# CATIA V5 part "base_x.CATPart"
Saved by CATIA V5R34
Part number: Part2
Bounding box of the stored display mesh (mm): x -37.1 to 14, y -14 to 32, z -13.1 to 13.1
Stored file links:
  C:\Users\Apolinar\Desktop\cnc\base_x.CATPart
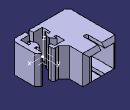
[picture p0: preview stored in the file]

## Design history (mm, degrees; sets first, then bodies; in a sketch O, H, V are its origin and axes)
AxisSystem1: origin (0, 0, 0), X (1, 0, 0), Y (0, 1, 0), Z (0, 0, 1)
Body1 (main body)
  DatumSurface1 to DatumSurface3
  DatumCurve1
  DatumPoint1
  DatumCurve2
  DatumCurve3
  DatumSurface4
  DatumCurve4
  Sketch1 on XY plane of AxisSystem1, origin (0, 0, 0), H (1, 0, 0), V (0, 1, 0)
    point P1 (-11.55, 0)
    line L1 (14, 10) -> (14, -14)
    line L2 (14, -14) -> (-37.1, -14)
    line L3 (-37.1, -14) -> (-37.1, 12)
    line L4 (-37.1, 12) -> (1.95, 12)
    reference intersected line E1 (-8.5, 10) -> (-3.75, 10) from face of DatumSurface1
    reference intersected line E2 (10, -3.75) -> (10, -8.5) from face of DatumSurface2
    line L5 (10, 10) -> (10, 2.5)
    line L6 (10, -10) -> (-10, -10)
    line L7 (-10, -10) -> (-10, -2.5)
    line L8 (-10, 10) -> (-1.05, 10)
    point P7 (-10, -10)
    point P8 (-10, 10)
    reference intersected line E3 through (-33.1, 0) direction (0, 1) from face of DatumSurface3
    point P9 (-10, 2.5)
    line L9 (-10, 2.5) -> (-8, 2.5)
    point P10 (-8, 2.5)
    point P11 (-8, -2.5)
    line L10 (-8, -2.5) -> (-10, -2.5)
    point P12 (-10, -2.5)
    line L11 (-10, 2.5) -> (-10, 10)
    line L12 (-1.05, 10) -> (-1.05, 6.5)
    line L13 (-1.05, 6.5) -> (1.95, 6.5)
    line L14 (1.95, 6.5) -> (1.95, 12)
    reference projected line E4 (-3.05, 9) -> (-3.05, 9.3) from edge of DatumCurve3
    line L15 (10, 10) -> (14, 10)
    reference intersected line E5 (3.75, 10) -> (8.5, 10) from face of DatumSurface4
    reference projected line E6 (-0.9196, 4.5) -> (-3.2919, 4.5) from edge of DatumCurve4
    point P18 (10, -2.5)
    point P19 (10, 2.5)
    line L16 (10, -2.5) -> (10, -10)
    line L17 (-8, 2.5) -> (-8, 5.5)
    point P20 (-8, 5.5)
    line L18 (-8, 5.5) -> (-5, 1.5)
    point P21 (-5, 1.5)
    line L19 (-5, 1.5) -> (-5, 0)
    point P22 (-5, 0)
    point P23 (-8, -5.5)
    point P24 (-8, -2.5)
    line L20 (-8, -2.5) -> (-8, -5.5)
    point P25 (-5, -1.5)
    line L21 (-8, -5.5) -> (-5, -1.5)
    point P26 (-5, 0)
    line L22 (-5, -1.5) -> (-5, 0)
    point P27 (0, 0)
    point P28 (8, 2.5)
    point P29 (8, -2.5)
    point P30 (8, 5.5)
    point P31 (5, 1.5)
    point P32 (5, 0)
    point P33 (8, -5.5)
    point P34 (8, -2.5)
    point P35 (5, -1.5)
    point P36 (5, 0)
    line L23 (8, 2.5) -> (8, 5.5)
    line L24 (8, 5.5) -> (5, 1.5)
    line L25 (5, 1.5) -> (5, 0)
    line L26 (8, -2.5) -> (8, -5.5)
    line L27 (8, -5.5) -> (5, -1.5)
    line L28 (5, -1.5) -> (5, 0)
    point P37 (10, 2.5)
    line L29 (10, 2.5) -> (8, 2.5)
    point P38 (10, -2.5)
    line L30 (8, -2.5) -> (10, -2.5)
    distance E1 L4 = 2
    distance E2 L1 = 4
    length L6 = 20
    distance E3 L3 = 4
    distance L6 L2 = 4
    length L9 = 2
    distance P7 P8 = 20
    distance E4 L12 = 2
    length L13 = 3
    distance L13 E6 = 2
    distance L9 H = 2.5
    distance H P21 = 1.5
    distance L17 L19 = 3
    distance P20 H = 5.5
    coincidence: P1 H, P9 L7, L7 L11, L15 E5, L5 L16, P22 H, P11 P24
    horizontal: L2 H, L4 H, L6 H, L8 H, L9 H, L10 H, L13 H, L15 H
    vertical: L3 V, L5 V, L7 V, L11 V, L12 V, L14 V, L17 V, L19 V
    equidistance: L1 L3 P1, L5 L7 O, L6 L8 O
    symmetry: P12 P18 V, P9 P19 V, P20 P23 H, P10 P24 H, L17 L20 H, P21 P25 H, L18 L21 H, P22 P26 H, L19 L22 H, O P27 V, P10 P28 V, P11 P29 V, P20 P30 V, P21 P31 V, P22 P32 V, P23 P33 V, P24 P34 V, P25 P35 V, P26 P36 V, L17 L23 V, L18 L24 V, L19 L25 V, L20 L26 V, L21 L27 V, L22 L28 V, P9 P37 V, L9 L29 V, P12 P38 V, L10 L30 V
  Pad1: profile Sketch1, direction (0, 0, 1), length 13.1, mirrored extent
  DatumSurface5
  Sketch2 on face of Pad1, origin (0, 13.2, 0), H (-1, 0, 0), V (0, 0, 1)
    point P1 (22.95, 0)
    line L1 (33.1, 10.15) -> (33.1, -10.15)
    line L2 (33.1, -10.15) -> (12.8, -10.15)
    line L3 (12.8, -10.15) -> (12.8, 10.15)
    line L4 (12.8, 10.15) -> (33.1, 10.15)
    reference intersected line E1 (33.1, 8.45) -> (33.1, 3.7) from face of DatumSurface5
    length L4 = 20.3
    length L1 = 20.3
    coincidence: P1 H, L1 E1
    vertical: L1 V, L3 V
    horizontal: L2 H, L4 H
    equidistance: L1 L3 P1, L2 L4 P1
  Pocket1: profile Sketch2, direction (0, -1, 0), length 23
  Sketch3 on face of Pad1 from Sketch1.L4, origin (0, 12, 0), H (-1, 0, 0), V (0, 0, 1)
    construction line L1 (0, 5.1) -> (0, 13.1)
    point P1 (0, 5.1)
    point P2 (0, 13.1)
    line L2 (-1.75, 5.1) -> (-1.75, 13.1)
    line L3 (1.75, 13.1) -> (1.75, 5.1)
    arc A1 centre (0, 13.1) radius 1.75 from (-1.75, 13.1) to (1.75, 13.1) cw
    arc A2 centre (0, 5.1) radius 1.75 from (1.75, 5.1) to (-1.75, 5.1) cw
    point P3 (-1.75, 5.1)
    point P4 (-1.75, 13.1)
    point P5 (1.75, 13.1)
    point P6 (1.75, 5.1)
    reference projected line E1 (-1.95, 13.1) -> (37.1, 13.1) from edge [face of Pad1 from Sketch1.L4 | end face of Pad1]
    construction line L4 (0, -5.1) -> (0, -13.1)
    point P9 (-1.75, -5.1)
    point P10 (-1.75, -13.1)
    point P11 (1.75, -13.1)
    point P12 (1.75, -5.1)
    line L5 (-1.75, -5.1) -> (-1.75, -13.1)
    line L6 (1.75, -13.1) -> (1.75, -5.1)
    arc A3 centre (0, -13.1) radius 1.75 from (-1.75, -13.1) to (1.75, -13.1) ccw
    arc A4 centre (0, -5.1) radius 1.75 from (1.75, -5.1) to (-1.75, -5.1) ccw
    distance L1 L2 = 1.75
    length L1 = 8
    coincidence: P1 V, P2 E1
    vertical: L1 V
    tangency: A1 L2, A2 L2, A1 L3, A2 L3
    symmetry: L1 L4 H, P3 P9 H, P4 P10 H, P5 P11 H, P6 P12 H, L2 L5 H, L3 L6 H, A1 A3 H, A2 A4 H
  Pocket2: profile Sketch3, direction (0, -1, 0), length 30, opposite side length -10
  DatumCurve5
  Sketch4 on face of Pad1 from Sketch1.L4, origin (0, 12, 0), H (-1, 0, 0), V (0, 0, 1)
    point P1 (22.45, 0)
    line L1 (37.1, 13.1) -> (37.1, -13.1)
    line L2 (37.1, -13.1) -> (7.8, -13.1)
    line L3 (7.8, -13.1) -> (7.8, 13.1)
    line L4 (7.8, 13.1) -> (37.1, 13.1)
    reference projected line E1 (-1.95, 13.1) -> (37.1, 13.1) from edge [face of Pad1 from Sketch1.L4 | end face of Pad1]
    reference projected line E2 (37.1, -13.1) -> (37.1, 13.1) from edge [face of Pad1 from Sketch1.L3 | face of Pad1 from Sketch1.L4]
    reference projected line E3 (12.8, -10.15) -> (12.8, 10.15) from edge [face of Pocket1 from Sketch2.L3 | face of Pad1 from Sketch1.L4]
    point P6 (22.95, 0)
    line L5 (33.1, 10.15) -> (33.1, -10.15)
    line L6 (33.1, -10.15) -> (12.8, -10.15)
    line L7 (12.8, -10.15) -> (12.8, 10.15)
    line L8 (12.8, 10.15) -> (33.1, 10.15)
    reference projected line E4 (12.8, 10.15) -> (33.1, 10.15) from edge [face of Pocket1 from Sketch2.L4 | face of Pad1 from Sketch1.L4]
    reference projected line E5 (33.1, 10.15) -> (33.1, -10.15) from edge [face of Pocket1 from Sketch2.L1 | face of Pad1 from Sketch1.L4]
    distance L3 E3 = 5
    coincidence: P1 H, L4 E1, E2 L1, P6 H, E4 L8, L5 E5, E3 L7
    vertical: L1 V, L3 V, L5 V, L7 V
    horizontal: L2 H, L4 H, L6 H, L8 H
    equidistance: L1 L3 P1, L2 L4 P1, L5 L7 P6, L6 L8 P6
  Pad2: profile Sketch4, direction (0, 1, 0), length 20
  Chamfer1: length 3, angle 45, on edge [face of Pad1 from Sketch1.L1 | face of Pad1 from Sketch1.L2]; edge [face of Pad1 from Sketch1.L15 | face of Pad1 from Sketch1.L1]; edge [face of Pad1 from Sketch1.L2 | face of Pad2]; edge [face of Pad2 | end face of Pad2] (x3); edge [face of Pad2 from Sketch4.L3 | end face of Pad2]
  Chamfer2: length 5, angle 45, on edge [face of Pad1 from Sketch1.L4 | face of Pad2 from Sketch4.L3]
  DatumCurve6
  Sketch5 on face of Pad2, origin (0, 0, 13.1), H (1, 0, 0), V (0, 1, 0)
    construction line L1 (-23.1, 17) -> (-23.1, 32)
    point P2 (-23.1, 32)
    line L2 (-24.85, 17) -> (-24.85, 32)
    line L3 (-21.35, 32) -> (-21.35, 17)
    arc A1 centre (-23.1, 32) radius 1.75 from (-24.85, 32) to (-21.35, 32) cw
    arc A2 centre (-23.1, 17) radius 1.75 from (-21.35, 17) to (-24.85, 17) cw
    reference projected line E1 through (-19.35, 0) direction (0, 1) from edge of DatumCurve6
    reference projected line E2 (-37.1, 32) -> (-7.8, 32) from edge [face of Pad2 | end face of Pad2]
    distance L1 L2 = 1.75
    distance L1 E1 = 3.75
    length L1 = 15
    vertical: L1 V
    tangency: A1 L2, A2 L2, A1 L3, A2 L3
    coincidence: P2 E2
  Pocket3: profile Sketch5, direction (0, 0, -1), through (limit type 3)
  Fillet1: radius 1, on edge [face of Pad1 from Sketch1.L13 | face of Pad1 from Sketch1.L12]; edge [face of Pad1 from Sketch1.L14 | face of Pad1 from Sketch1.L13]; edge [face of Pad1 from Sketch1.L12 | face of Pad1 from Sketch1.L8]
  DatumSurface6 to DatumSurface8
  Fillet2: radius 2, on edge [face of Pad1 from Sketch1.L4 | face of Pad1 from Sketch1.L14]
